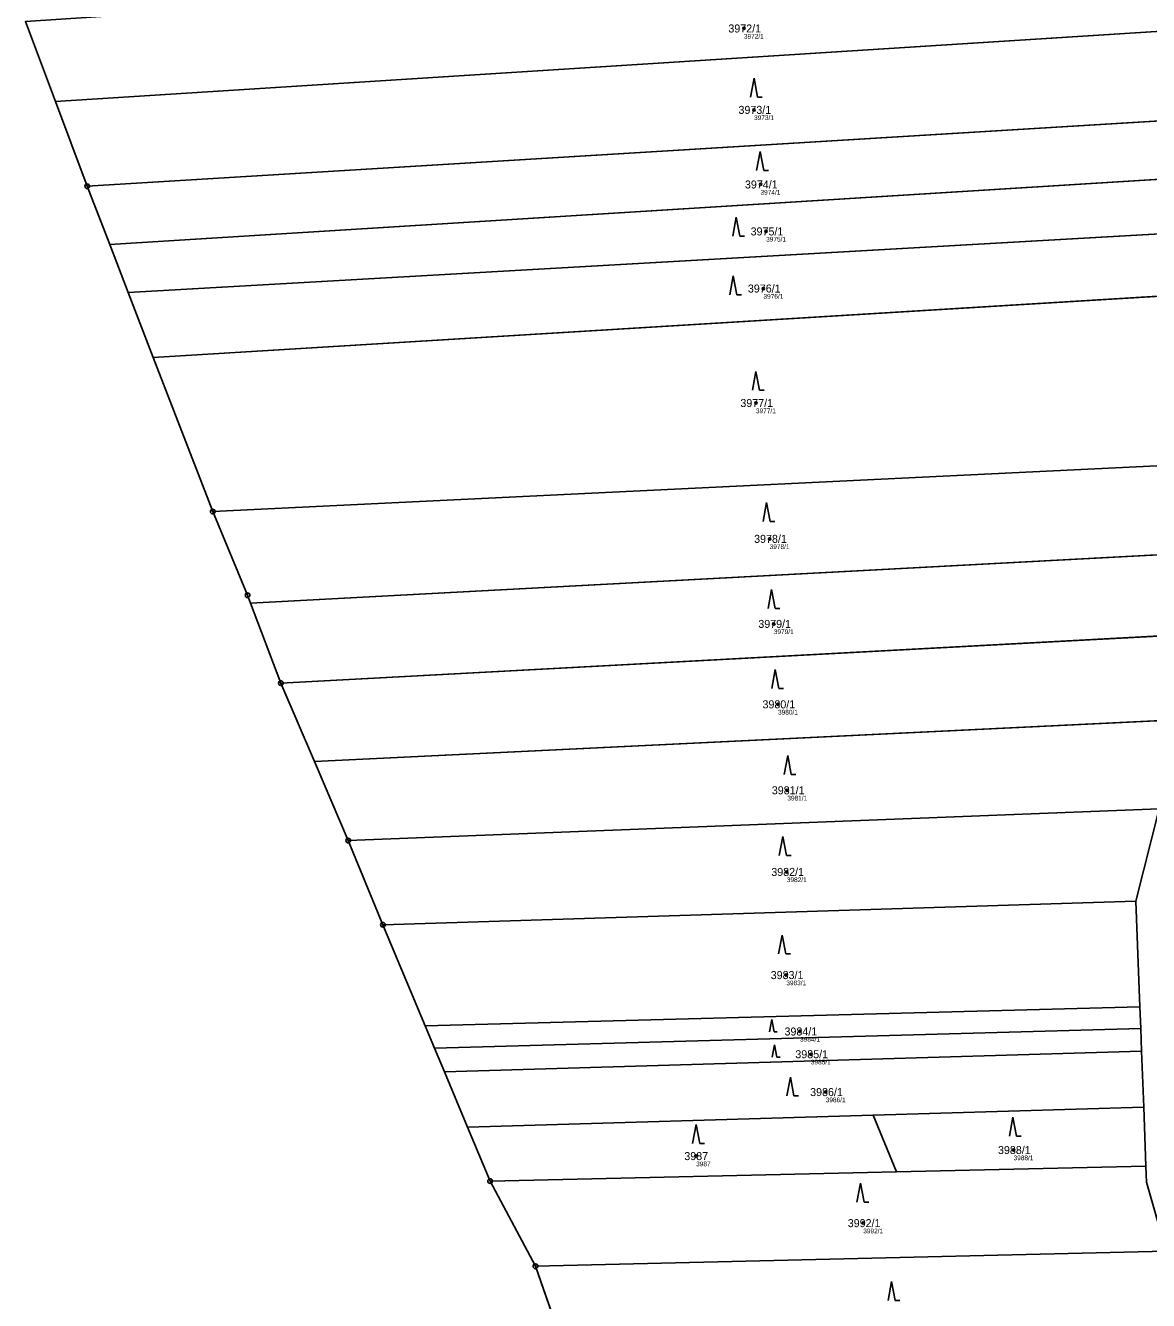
# Model space of a CAD drawing. Extents: x -658203 to -653176, y -1156738 to -1151709.
# Drawn here: x -657359.8 to -657121.2, y -1154514.8 to -1154244 of the extents above; entities that cross this region are included whole.
import ezdxf

# ---------------------------------------------------------------- set-up
doc = ezdxf.new("R2010")
doc.units = 0
for name, color, linetype in [('Vrstva 1', 7, 'Continuous'), ('Vrstva 2', 7, 'Continuous'), ('Vrstva 3', 7, 'Continuous'), ('Vrstva 50', 7, 'Continuous'), ('Vrstva 51', 7, 'Continuous'), ('Vrstva 8', 7, 'Continuous')]:
    doc.layers.add(name, color=color, linetype=linetype)

msp = doc.modelspace()

# ---------------------------------------------------------------- linework, layer by layer
at = {"layer": 'Vrstva 1'}
for p, q in [((-657353.46, -1154260.1), (-657359.83, -1154243.11)), ((-657353.46, -1154260.1), (-657100.61, -1154244.05)), ((-657346.72, -1154278.09), (-657353.46, -1154260.1)), ((-657346.72, -1154278.09), (-657097.75, -1154262.94)), ((-657341.93, -1154290.49), (-657095.9, -1154275.2)), ((-657341.93, -1154290.49), (-657346.72, -1154278.09)), ((-657094.98, -1154286.86), (-657338, -1154300.68)), ((-657338, -1154300.68), (-657341.93, -1154290.49)), ((-657332.68, -1154314.47), (-657338, -1154300.68)), ((-657332.68, -1154314.47), (-657096.02, -1154300.05)), ((-657320.04, -1154347.21), (-657332.68, -1154314.47)), ((-657320.04, -1154347.21), (-657106.24, -1154336.85)), ((-657312, -1154366.62), (-657108.76, -1154355.85)), ((-657305.56, -1154383.64), (-657312, -1154366.62)), ((-657305.56, -1154383.64), (-657109.51, -1154373.12)), ((-657298.44, -1154400.27), (-657305.56, -1154383.64)), ((-657298.44, -1154400.27), (-657114.11, -1154391.37)), ((-657291.24, -1154417.09), (-657298.44, -1154400.27)), ((-657291.24, -1154417.09), (-657118.9, -1154410.37)), ((-657118.9, -1154410.37), (-657123.83, -1154429.95)), ((-657283.88, -1154434.95), (-657291.24, -1154417.09)), ((-657283.88, -1154434.95), (-657123.83, -1154429.95)), ((-657123.83, -1154429.95), (-657122.99, -1154452.37)), ((-657274.89, -1154456.42), (-657283.88, -1154434.95)), ((-657274.89, -1154456.42), (-657122.99, -1154452.37)), ((-657122.99, -1154452.37), (-657122.82, -1154457)), ((-657272.91, -1154461.16), (-657274.89, -1154456.42)), ((-657272.91, -1154461.16), (-657122.82, -1154457)), ((-657122.82, -1154457), (-657122.64, -1154461.82)), ((-657270.81, -1154466.17), (-657272.91, -1154461.16)), ((-657270.81, -1154466.17), (-657122.64, -1154461.82)), ((-657122.64, -1154461.82), (-657122.19, -1154473.67)), ((-657265.88, -1154477.95), (-657270.81, -1154466.17)), ((-657179.69, -1154475.38), (-657265.88, -1154477.95)), ((-657179.69, -1154475.38), (-657122.19, -1154473.67)), ((-657174.75, -1154487.43), (-657179.69, -1154475.38)), ((-657122.19, -1154473.67), (-657121.73, -1154486.22)), ((-657261.08, -1154489.4), (-657265.88, -1154477.95)), ((-657174.75, -1154487.43), (-657121.73, -1154486.22)), ((-657261.08, -1154489.4), (-657174.75, -1154487.43)), ((-657251.44, -1154507.51), (-657261.08, -1154489.4)), ((-657251.44, -1154507.51), (-657117.39, -1154504.26)), ((-657245.07, -1154525.71), (-657251.44, -1154507.51))]:
    msp.add_line(p, q, dxfattribs=at)
for points in [[(-657312, -1154366.62), (-657312.62, -1154364.98), (-657320.04, -1154347.21)], [(-657121.73, -1154486.22), (-657121.6, -1154489.65), (-657117.39, -1154504.26)]]:
    msp.add_lwpolyline(points, dxfattribs=at)
at = {"layer": 'Vrstva 3'}
for p, q in [((-657204.99, -1154255.17), (-657205.74, -1154259.17)), ((-657204.24, -1154259.17), (-657204.99, -1154255.17)), ((-657204.24, -1154259.17), (-657203.24, -1154259.17)), ((-657203.69, -1154270.74), (-657204.44, -1154274.74)), ((-657202.94, -1154274.74), (-657203.69, -1154270.74)), ((-657202.94, -1154274.74), (-657201.94, -1154274.74)), ((-657208.76, -1154284.67), (-657209.51, -1154288.67)), ((-657208.01, -1154288.67), (-657208.76, -1154284.67)), ((-657208.01, -1154288.67), (-657207.01, -1154288.67)), ((-657209.42, -1154297.13), (-657210.17, -1154301.13)), ((-657208.67, -1154301.13), (-657209.42, -1154297.13)), ((-657208.67, -1154301.13), (-657207.67, -1154301.13)), ((-657204.59, -1154317.44), (-657205.34, -1154321.44)), ((-657203.84, -1154321.44), (-657204.59, -1154317.44)), ((-657203.84, -1154321.44), (-657202.84, -1154321.44)), ((-657202.34, -1154345.28), (-657203.09, -1154349.28)), ((-657201.59, -1154349.28), (-657202.34, -1154345.28)), ((-657201.59, -1154349.28), (-657200.59, -1154349.28)), ((-657201.27, -1154363.78), (-657202.02, -1154367.78)), ((-657200.52, -1154367.78), (-657201.27, -1154363.78)), ((-657200.52, -1154367.78), (-657199.52, -1154367.78)), ((-657200.49, -1154380.75), (-657201.24, -1154384.75)), ((-657199.74, -1154384.75), (-657200.49, -1154380.75)), ((-657199.74, -1154384.75), (-657198.74, -1154384.75)), ((-657197.84, -1154399.01), (-657198.59, -1154403.01)), ((-657197.09, -1154403.01), (-657197.84, -1154399.01)), ((-657197.09, -1154403.01), (-657196.09, -1154403.01)), ((-657198.87, -1154416.23), (-657199.62, -1154420.23)), ((-657198.12, -1154420.23), (-657198.87, -1154416.23)), ((-657198.12, -1154420.23), (-657197.12, -1154420.23)), ((-657199.02, -1154437.15), (-657199.77, -1154441.15)), ((-657198.27, -1154441.15), (-657199.02, -1154437.15)), ((-657198.27, -1154441.15), (-657197.27, -1154441.15)), ((-657201.23, -1154455.05), (-657201.73, -1154457.73)), ((-657200.73, -1154457.73), (-657201.23, -1154455.05)), ((-657200.73, -1154457.73), (-657200.06, -1154457.73)), ((-657200.64, -1154460.43), (-657201.14, -1154463.11)), ((-657200.14, -1154463.11), (-657200.64, -1154460.43)), ((-657200.14, -1154463.11), (-657199.47, -1154463.11)), ((-657197.27, -1154467.3), (-657198.02, -1154471.3)), ((-657196.52, -1154471.3), (-657197.27, -1154467.3)), ((-657196.52, -1154471.3), (-657195.52, -1154471.3)), ((-657149.96, -1154475.86), (-657150.71, -1154479.86)), ((-657149.21, -1154479.86), (-657149.96, -1154475.86)), ((-657217.3, -1154477.4), (-657218.05, -1154481.4)), ((-657216.55, -1154481.4), (-657217.3, -1154477.4)), ((-657149.21, -1154479.86), (-657148.21, -1154479.86)), ((-657216.55, -1154481.4), (-657215.55, -1154481.4)), ((-657182.37, -1154489.85), (-657183.12, -1154493.85)), ((-657181.62, -1154493.85), (-657182.37, -1154489.85)), ((-657181.62, -1154493.85), (-657180.62, -1154493.85)), ((-657175.75, -1154510.74), (-657176.5, -1154514.74)), ((-657175, -1154514.74), (-657175.75, -1154510.74)), ((-657175, -1154514.74), (-657174, -1154514.74))]:
    msp.add_line(p, q, dxfattribs=at)
at = {"layer": 'Vrstva 50'}
for centre in [(-657207.15, -1154244.58), (-657204.99, -1154261.87), (-657203.62, -1154277.72), (-657202.42, -1154287.69), (-657202.99, -1154299.82), (-657204.59, -1154324.14), (-657201.68, -1154352.99), (-657200.79, -1154371.06), (-657199.9, -1154388.14), (-657197.92, -1154406.4), (-657198.03, -1154423.74), (-657198.14, -1154445.65), (-657195.21, -1154457.63), (-657192.92, -1154462.46), (-657189.76, -1154470.5), (-657217.3, -1154484.1), (-657149.84, -1154482.81), (-657181.78, -1154498.34)]:
    msp.add_circle(centre, 0.25, dxfattribs=at)
at = {"layer": 'Vrstva 51'}
for points in [[(-657100.61, -1154244.05), (-657103.33, -1154226.11), (-657359.83, -1154243.11), (-657353.46, -1154260.1)], [(-657097.75, -1154262.94), (-657100.61, -1154244.05), (-657353.46, -1154260.1), (-657346.72, -1154278.09)], [(-657095.9, -1154275.2), (-657097.75, -1154262.94), (-657346.72, -1154278.09), (-657341.93, -1154290.49)], [(-657341.93, -1154290.49), (-657338, -1154300.68), (-657094.98, -1154286.86), (-657094.69, -1154283.18), (-657095.9, -1154275.2)], [(-657332.68, -1154314.47), (-657096.02, -1154300.05), (-657094.98, -1154286.86), (-657338, -1154300.68)], [(-657320.04, -1154347.21), (-657106.24, -1154336.85), (-657096.81, -1154310.16), (-657096.02, -1154300.05), (-657332.68, -1154314.47)], [(-657108.76, -1154355.85), (-657108.18, -1154342.35), (-657106.24, -1154336.85), (-657320.04, -1154347.21), (-657312.62, -1154364.98), (-657312, -1154366.62)], [(-657109.51, -1154373.12), (-657108.76, -1154355.85), (-657312, -1154366.62), (-657305.56, -1154383.64)], [(-657114.11, -1154391.37), (-657109.51, -1154373.12), (-657305.56, -1154383.64), (-657298.44, -1154400.27)], [(-657118.9, -1154410.37), (-657114.11, -1154391.37), (-657298.44, -1154400.27), (-657291.24, -1154417.09)], [(-657123.83, -1154429.95), (-657118.9, -1154410.37), (-657291.24, -1154417.09), (-657283.88, -1154434.95)], [(-657122.99, -1154452.37), (-657123.83, -1154429.95), (-657283.88, -1154434.95), (-657274.89, -1154456.42)], [(-657122.82, -1154457), (-657122.99, -1154452.37), (-657274.89, -1154456.42), (-657272.91, -1154461.16)], [(-657122.64, -1154461.82), (-657122.82, -1154457), (-657272.91, -1154461.16), (-657270.81, -1154466.17)], [(-657122.19, -1154473.67), (-657122.64, -1154461.82), (-657270.81, -1154466.17), (-657265.88, -1154477.95), (-657179.69, -1154475.38)], [(-657174.75, -1154487.43), (-657179.69, -1154475.38), (-657265.88, -1154477.95), (-657261.08, -1154489.4)], [(-657121.73, -1154486.22), (-657122.19, -1154473.67), (-657179.69, -1154475.38), (-657174.75, -1154487.43)], [(-657117.39, -1154504.26), (-657121.6, -1154489.65), (-657121.73, -1154486.22), (-657174.75, -1154487.43), (-657261.08, -1154489.4), (-657251.44, -1154507.51)], [(-657111.69, -1154524.05), (-657117.39, -1154504.26), (-657251.44, -1154507.51), (-657245.07, -1154525.71)]]:
    msp.add_lwpolyline(points, close=True, dxfattribs=at)
for points in [[(-657103.33, -1154226.11), (-657100.61, -1154244.05), (-657097.75, -1154262.94), (-657095.9, -1154275.2), (-657094.69, -1154283.18), (-657094.98, -1154286.86), (-657096.02, -1154300.05), (-657096.81, -1154310.16), (-657106.24, -1154336.85), (-657108.18, -1154342.35), (-657108.76, -1154355.85), (-657109.51, -1154373.12), (-657114.11, -1154391.37), (-657118.9, -1154410.37), (-657123.83, -1154429.95), (-657122.99, -1154452.37), (-657122.82, -1154457), (-657122.64, -1154461.82), (-657122.19, -1154473.67), (-657121.73, -1154486.22), (-657121.6, -1154489.65), (-657117.39, -1154504.26), (-657111.69, -1154524.05)], [(-657245.07, -1154525.71), (-657251.44, -1154507.51), (-657261.08, -1154489.4), (-657265.88, -1154477.95), (-657270.81, -1154466.17), (-657272.91, -1154461.16), (-657274.89, -1154456.42), (-657283.88, -1154434.95), (-657291.24, -1154417.09), (-657298.44, -1154400.27), (-657305.56, -1154383.64), (-657312, -1154366.62), (-657312.62, -1154364.98), (-657320.04, -1154347.21), (-657332.68, -1154314.47), (-657338, -1154300.68), (-657341.93, -1154290.49), (-657346.72, -1154278.09), (-657353.46, -1154260.1), (-657359.83, -1154243.11)]]:
    msp.add_lwpolyline(points, dxfattribs=at)
at = {"layer": 'Vrstva 8'}
for centre, radius in [((-657346.72, -1154278.09), 0.5), ((-657346.72, -1154278.09), 0.0303), ((-657320.04, -1154347.21), 0.5), ((-657320.04, -1154347.21), 0.0303), ((-657312.62, -1154364.98), 0.5), ((-657312.62, -1154364.98), 0.0303), ((-657305.56, -1154383.64), 0.5), ((-657305.56, -1154383.64), 0.0303), ((-657291.24, -1154417.09), 0.5), ((-657291.24, -1154417.09), 0.0303), ((-657283.88, -1154434.95), 0.5), ((-657283.88, -1154434.95), 0.0303), ((-657261.08, -1154489.4), 0.5), ((-657261.08, -1154489.4), 0.0303), ((-657251.44, -1154507.51), 0.5), ((-657251.44, -1154507.51), 0.0303)]:
    msp.add_circle(centre, radius, dxfattribs=at)

# ---------------------------------------------------------------- texts
at = {"layer": 'Vrstva 2'}
for s, p in [('3972/1', (-657210.45, -1154245.43)), ('3973/1', (-657208.3, -1154262.72)), ('3974/1', (-657206.93, -1154278.57)), ('3975/1', (-657205.72, -1154288.54)), ('3976/1', (-657206.3, -1154300.67)), ('3977/1', (-657207.9, -1154324.99)), ('3978/1', (-657204.98, -1154353.84)), ('3979/1', (-657204.09, -1154371.91)), ('3980/1', (-657203.2, -1154388.99)), ('3981/1', (-657201.22, -1154407.25)), ('3982/1', (-657201.33, -1154424.59)), ('3983/1', (-657201.45, -1154446.5)), ('3984/1', (-657198.52, -1154458.48)), ('3985/1', (-657196.22, -1154463.31)), ('3986/1', (-657193.07, -1154471.35)), ('3987', (-657219.81, -1154484.95)), ('3988/1', (-657153.15, -1154483.66)), ('3992/1', (-657185.08, -1154499.19))]:
    msp.add_text(s, height=1.7, dxfattribs=at).set_placement(p)
at = {"layer": 'Vrstva 50'}
for s, p in [('3972/1', (-657207.15, -1154246.74)), ('3973/1', (-657204.99, -1154264.03)), ('3974/1', (-657203.62, -1154279.88)), ('3975/1', (-657202.42, -1154289.85)), ('3976/1', (-657202.99, -1154301.98)), ('3977/1', (-657204.59, -1154326.3)), ('3978/1', (-657201.68, -1154355.15)), ('3979/1', (-657200.79, -1154373.22)), ('3980/1', (-657199.9, -1154390.3)), ('3981/1', (-657197.92, -1154408.56)), ('3982/1', (-657198.03, -1154425.9)), ('3983/1', (-657198.14, -1154447.81)), ('3984/1', (-657195.21, -1154459.79)), ('3985/1', (-657192.92, -1154464.62)), ('3986/1', (-657189.76, -1154472.66)), ('3988/1', (-657149.84, -1154484.97)), ('3987', (-657217.3, -1154486.26)), ('3992/1', (-657181.78, -1154500.5))]:
    msp.add_text(s, height=1, dxfattribs=at).set_placement(p)

doc.saveas('drawing.dxf')
